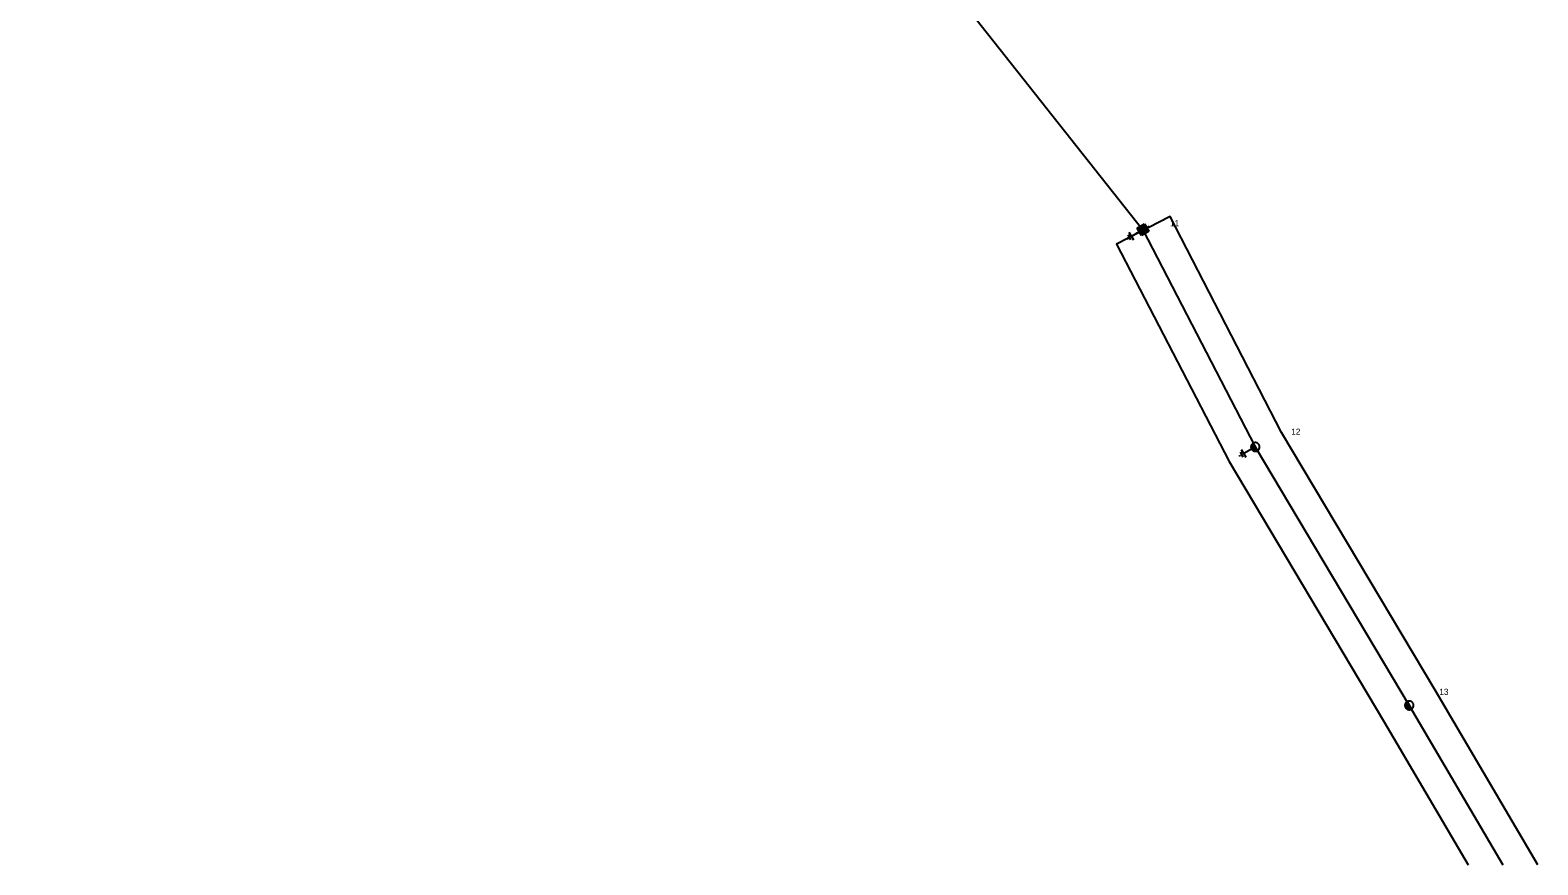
# Model space of a CAD drawing. Extents: x -762349 to -761250, y -1154000 to -1153000.
# Drawn here: x -762258.7 to -761832.1, y -1154000 to -1153763.9 of the extents above; entities that cross this region are included whole.
import ezdxf

# ---------------------------------------------------------------- set-up
doc = ezdxf.new("R2010")
doc.units = 0
for name, color, linetype in [('Vrstva 1', 7, 'Continuous'), ('Vrstva 13', 7, 'Continuous'), ('Vrstva 14', 7, 'Continuous'), ('Vrstva 15', 7, 'Continuous'), ('Vrstva 35', 7, 'Continuous')]:
    doc.layers.add(name, color=color, linetype=linetype)

msp = doc.modelspace()

# ---------------------------------------------------------------- linework, layer by layer
at = {"layer": 'Vrstva 1'}
msp.add_lwpolyline([(-762258.42, -1153358.35), (-762258.66, -1153401.76), (-762238.55, -1153465.08), (-762187.96, -1153511.89), (-761943.79, -1153820.37), (-761912.01, -1153881.81), (-761868.44, -1153954.91), (-761841.93, -1154000)], dxfattribs=at)
at = {"layer": 'Vrstva 13'}
for points in [[(-761945.473, -1153819.923), (-761943.345, -1153818.695)], [(-761944.244, -1153822.051), (-761945.473, -1153819.923)], [(-761945.07, -1153820.045), (-761943.474, -1153819.124)], [(-761944.148, -1153821.641), (-761945.07, -1153820.045)], [(-761944.634, -1153820.148), (-761943.569, -1153819.533)], [(-761944.019, -1153821.212), (-761944.634, -1153820.148)], [(-761944.181, -1153820.241), (-761943.649, -1153819.934)], [(-761943.874, -1153820.773), (-761944.181, -1153820.241)], [(-761942.553, -1153820.719), (-761944.148, -1153821.641)], [(-761942.955, -1153820.597), (-761944.019, -1153821.212)], [(-761943.342, -1153820.466), (-761943.874, -1153820.773)], [(-761943.649, -1153819.934), (-761943.342, -1153820.466)], [(-761943.569, -1153819.533), (-761942.955, -1153820.597)], [(-761943.474, -1153819.124), (-761942.553, -1153820.719)], [(-761943.345, -1153818.695), (-761942.116, -1153820.822)], [(-761942.73, -1153819.758), (-761942.083, -1153819.384)], [(-761944.858, -1153820.987), (-761945.506, -1153821.361)], [(-761942.116, -1153820.822), (-761944.244, -1153822.051)], [(-761911.404, -1153882.868), (-761911.296, -1153882.798), (-761911.196, -1153882.717), (-761911.105, -1153882.626), (-761911.024, -1153882.526), (-761910.954, -1153882.418), (-761910.896, -1153882.304), (-761910.85, -1153882.184), (-761910.816, -1153882.06), (-761910.796, -1153881.933), (-761910.789, -1153881.804), (-761910.796, -1153881.676), (-761910.816, -1153881.549), (-761910.85, -1153881.424), (-761910.895, -1153881.304), (-761910.954, -1153881.19), (-761911.024, -1153881.082), (-761911.105, -1153880.982), (-761911.196, -1153880.891), (-761911.295, -1153880.81), (-761911.403, -1153880.74), (-761911.518, -1153880.682), (-761911.638, -1153880.636), (-761911.762, -1153880.602), (-761911.89, -1153880.582), (-761912.018, -1153880.576), (-761912.146, -1153880.583), (-761912.273, -1153880.602), (-761912.397, -1153880.636), (-761912.517, -1153880.682), (-761912.632, -1153880.74), (-761912.74, -1153880.81), (-761912.84, -1153880.891), (-761912.931, -1153880.982), (-761913.012, -1153881.082), (-761913.081, -1153881.19), (-761913.14, -1153881.304), (-761913.186, -1153881.424), (-761913.219, -1153881.549), (-761913.239, -1153881.676), (-761913.246, -1153881.804), (-761913.239, -1153881.933), (-761913.219, -1153882.059), (-761913.186, -1153882.184), (-761913.14, -1153882.304), (-761913.081, -1153882.418), (-761913.012, -1153882.526), (-761912.931, -1153882.626), (-761912.84, -1153882.717), (-761912.74, -1153882.798), (-761912.632, -1153882.868), (-761912.517, -1153882.926), (-761912.397, -1153882.973), (-761912.273, -1153883.005), (-761912.146, -1153883.026), (-761912.018, -1153883.032), (-761911.889, -1153883.026), (-761911.762, -1153883.005), (-761911.638, -1153882.972), (-761911.518, -1153882.926), (-761911.404, -1153882.868)], [(-761913.175, -1153881.626), (-761912.465, -1153882.856)], [(-761913.06, -1153881.249), (-761912.072, -1153882.961)], [(-761912.897, -1153880.956), (-761911.755, -1153882.934)], [(-761912.627, -1153880.733), (-761911.399, -1153882.861)], [(-761867.815, -1153955.957), (-761867.708, -1153955.885), (-761867.61, -1153955.802), (-761867.521, -1153955.71), (-761867.441, -1153955.608), (-761867.373, -1153955.5), (-761867.317, -1153955.384), (-761867.273, -1153955.263), (-761867.242, -1153955.139), (-761867.224, -1153955.011), (-761867.219, -1153954.882), (-761867.228, -1153954.754), (-761867.251, -1153954.628), (-761867.286, -1153954.504), (-761867.334, -1153954.385), (-761867.395, -1153954.271), (-761867.466, -1153954.165), (-761867.549, -1153954.066), (-761867.642, -1153953.977), (-761867.743, -1153953.898), (-761867.852, -1153953.829), (-761867.968, -1153953.773), (-761868.089, -1153953.729), (-761868.214, -1153953.698), (-761868.341, -1153953.68), (-761868.469, -1153953.676), (-761868.597, -1153953.685), (-761868.724, -1153953.707), (-761868.848, -1153953.742), (-761868.967, -1153953.79), (-761869.08, -1153953.851), (-761869.187, -1153953.923), (-761869.285, -1153954.005), (-761869.375, -1153954.098), (-761869.454, -1153954.2), (-761869.522, -1153954.309), (-761869.578, -1153954.424), (-761869.622, -1153954.545), (-761869.654, -1153954.67), (-761869.671, -1153954.797), (-761869.676, -1153954.925), (-761869.667, -1153955.054), (-761869.645, -1153955.18), (-761869.609, -1153955.304), (-761869.561, -1153955.423), (-761869.501, -1153955.536), (-761869.429, -1153955.643), (-761869.346, -1153955.741), (-761869.254, -1153955.831), (-761869.152, -1153955.91), (-761869.044, -1153955.978), (-761868.928, -1153956.035), (-761868.807, -1153956.079), (-761868.682, -1153956.11), (-761868.555, -1153956.127), (-761868.426, -1153956.132), (-761868.298, -1153956.123), (-761868.172, -1153956.101), (-761868.048, -1153956.065), (-761867.929, -1153956.017), (-761867.815, -1153955.957)], [(-761869.608, -1153954.746), (-761868.877, -1153955.963)], [(-761869.5, -1153954.367), (-761868.482, -1153956.062)], [(-761869.342, -1153954.071), (-761868.165, -1153956.029)], [(-761869.076, -1153953.844), (-761867.81, -1153955.95)]]:
    msp.add_lwpolyline(points, dxfattribs=at)
at = {"layer": 'Vrstva 15'}
for points in [[(-761948.116, -1153822.871), (-761948.244, -1153822.65)], [(-761947.983, -1153823.101), (-761948.116, -1153822.871)], [(-761947.187, -1153823.221), (-761947.974, -1153821.857)], [(-761946.409, -1153823.329), (-761947.659, -1153821.164)], [(-761944.869, -1153820.996), (-761947.034, -1153822.246)], [(-761916.336, -1153884.311), (-761916.464, -1153884.09)], [(-761916.203, -1153884.542), (-761916.336, -1153884.311)], [(-761915.407, -1153884.661), (-761916.194, -1153883.297)], [(-761914.629, -1153884.769), (-761915.879, -1153882.604)], [(-761913.089, -1153882.436), (-761915.254, -1153883.686)]]:
    msp.add_lwpolyline(points, dxfattribs=at)
at = {"layer": 'Vrstva 35'}
msp.add_lwpolyline([(-761832.06, -1154000), (-761861.13, -1153950.58), (-761904.58, -1153877.68), (-761936.14, -1153816.65), (-761951.24, -1153824.46), (-761919.44, -1153885.94), (-761875.75, -1153959.24), (-761851.79, -1154000)], dxfattribs=at)

# ---------------------------------------------------------------- texts
at = {"layer": 'Vrstva 14'}
for s, p in [('11', (-761936.12, -1153819.38)), ('12', (-761901.84, -1153878.36)), ('13', (-761859.93, -1153951.93))]:
    msp.add_text(s, height=1.74, dxfattribs=at).set_placement(p)

doc.saveas('drawing.dxf')
